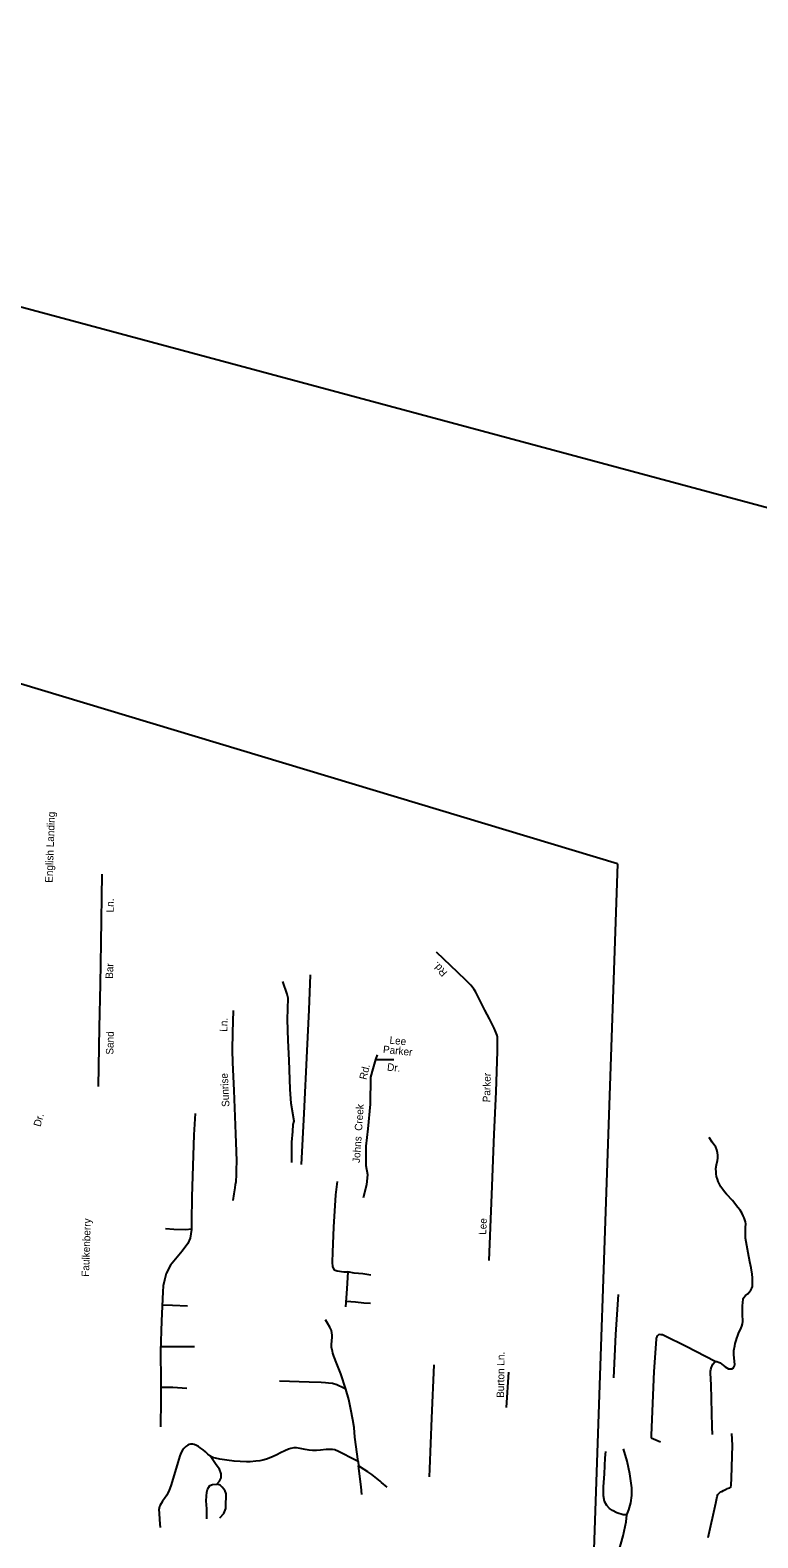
# Model space of a CAD drawing. Extents: x 2308163 to 2335412, y -96774 to 127732.
# Drawn here: x 2322097.3 to 2322147.2, y 82546.6 to 82650.1 of the extents above; entities that cross this region are included whole.
import ezdxf

# ---------------------------------------------------------------- set-up
doc = ezdxf.new("R2010")
doc.units = 0
for name, color, linetype in [('Old_Level_10', 7, 'Continuous'), ('Old_Level_35', 7, 'Continuous'), ('Old_Level_63', 7, 'Continuous')]:
    doc.layers.add(name, color=color, linetype=linetype)

msp = doc.modelspace()

# ---------------------------------------------------------------- linework, layer by layer
at = {"layer": 'Old_Level_35'}
for p, q in [((2322139.92, 82553.69), (2322139.91, 82553.51)), ((2322139.91, 82553.51), (2322140.56, 82553.24)), ((2322144.11, 82553.73), (2322144.09, 82554.26)), ((2322119.81, 82551.88), (2322119.85, 82551.59)), ((2322120.02, 82550.15), (2322119.85, 82551.59)), ((2322124.71, 82550.84), (2322124.73, 82551.38)), ((2322120.08, 82549.62), (2322120.02, 82550.15)), ((2322106.2, 82547.89), (2322106.23, 82547.36))]:
    msp.add_line(p, q, dxfattribs=at)
for points in [[(2322102.02, 82577.61), (2322102.09, 82581.67), (2322102.15, 82584.64), (2322102.2, 82587.48), (2322102.26, 82592.18)], [(2322128.8, 82565.69), (2322128.98, 82570.2), (2322129.14, 82574.34), (2322129.28, 82577.26), (2322129.38, 82580.04), (2322129.38, 82580.27), (2322129.38, 82580.55), (2322129.38, 82580.82), (2322129.37, 82581.01), (2322129.34, 82581.12), (2322129.27, 82581.34), (2322129.15, 82581.61), (2322128.82, 82582.27), (2322128.51, 82582.86), (2322127.89, 82584.08), (2322127.78, 82584.28), (2322127.55, 82584.57), (2322127.21, 82584.92), (2322126.66, 82585.44), (2322125.18, 82586.83)], [(2322115.26, 82572.41), (2322115.26, 82573.15), (2322115.26, 82573.44), (2322115.28, 82573.63), (2322115.28, 82573.8), (2322115.34, 82574.53), (2322115.37, 82575), (2322115.42, 82575.25), (2322115.23, 82576.46), (2322115.16, 82577.44), (2322115.09, 82579.43), (2322115.01, 82580.78), (2322114.98, 82582.22), (2322115.02, 82583.68), (2322114.96, 82583.95), (2322114.66, 82584.82)], [(2322115.94, 82572.27), (2322116.11, 82575.76), (2322116.33, 82580.07), (2322116.46, 82582.88), (2322116.56, 82585.28)], [(2322111.42, 82574.36), (2322111.32, 82577.35), (2322111.22, 82579.26), (2322111.2, 82580.1), (2322111.22, 82581.32), (2322111.28, 82582.84)], [(2322121.12, 82579.8), (2322121.01, 82579.47), (2322120.83, 82578.84), (2322120.67, 82578.25), (2322120.65, 82576.41), (2322120.47, 82574.71), (2322120.35, 82573.53), (2322120.34, 82572.2), (2322120.46, 82571.58), (2322120.4, 82570.87), (2322120.17, 82569.99)], [(2322121.01, 82579.47), (2322122.26, 82579.46)], [(2322108.64, 82575.77), (2322108.56, 82574.31), (2322108.42, 82570.04), (2322108.4, 82568.35), (2322108.4, 82567.8), (2322108.3, 82567.22), (2322108.13, 82566.85), (2322107.75, 82566.32), (2322107.29, 82565.76), (2322106.96, 82565.37), (2322106.66, 82564.79), (2322106.53, 82564.32), (2322106.44, 82563.93), (2322106.42, 82563.54), (2322106.33, 82561.55), (2322106.27, 82559.43), (2322106.29, 82557.42), (2322106.29, 82556.09), (2322106.27, 82554.26)], [(2322111.24, 82569.8), (2322111.32, 82570.25), (2322111.39, 82570.66), (2322111.41, 82570.89), (2322111.45, 82571.09), (2322111.47, 82571.56), (2322111.48, 82571.89), (2322111.5, 82572.5), (2322111.48, 82573.16), (2322111.42, 82574.36)], [(2322144.3, 82558.75), (2322144.35, 82558.75), (2322144.42, 82558.75), (2322144.52, 82558.71), (2322144.66, 82558.65), (2322144.75, 82558.57), (2322144.99, 82558.39), (2322145.11, 82558.31), (2322145.21, 82558.25), (2322145.34, 82558.24), (2322145.45, 82558.25), (2322145.55, 82558.31), (2322145.59, 82558.37), (2322145.63, 82558.45), (2322145.65, 82558.54), (2322145.58, 82559.2), (2322145.59, 82559.37), (2322145.59, 82559.5), (2322145.65, 82559.83), (2322145.68, 82559.98), (2322145.73, 82560.2), (2322145.78, 82560.35), (2322145.85, 82560.53), (2322145.93, 82560.73), (2322146.03, 82560.94), (2322146.13, 82561.18), (2322146.18, 82561.34), (2322146.2, 82561.49), (2322146.19, 82561.61), (2322146.18, 82561.88), (2322146.17, 82562.16), (2322146.18, 82562.53), (2322146.19, 82562.85), (2322146.21, 82562.97), (2322146.22, 82563.07), (2322146.26, 82563.15), (2322146.39, 82563.28), (2322146.53, 82563.4), (2322146.64, 82563.51), (2322146.74, 82563.65), (2322146.81, 82563.77), (2322146.85, 82563.9), (2322146.86, 82564.06), (2322146.86, 82564.24), (2322146.85, 82564.49), (2322146.83, 82564.74), (2322146.76, 82565.18), (2322146.67, 82565.59), (2322146.57, 82566.21), (2322146.43, 82566.97), (2322146.39, 82567.21), (2322146.38, 82567.39), (2322146.37, 82567.63), (2322146.39, 82567.95), (2322146.4, 82568.19), (2322146.38, 82568.33), (2322146.34, 82568.47), (2322146.29, 82568.6), (2322146.22, 82568.75), (2322146.12, 82568.96), (2322146.01, 82569.13), (2322145.86, 82569.32), (2322145.5, 82569.79), (2322145.08, 82570.24), (2322144.95, 82570.39), (2322144.83, 82570.55), (2322144.69, 82570.74), (2322144.6, 82570.91), (2322144.51, 82571.1), (2322144.45, 82571.25), (2322144.4, 82571.45), (2322144.37, 82571.63), (2322144.36, 82571.75), (2322144.35, 82571.99), (2322144.38, 82572.24), (2322144.45, 82572.55), (2322144.48, 82572.7), (2322144.49, 82572.91), (2322144.46, 82573.06), (2322144.41, 82573.28), (2322144.35, 82573.46), (2322144.09, 82573.81), (2322143.88, 82574.11)], [(2322118.37, 82571.09), (2322118.27, 82570.19), (2322118.13, 82567.96), (2322118.05, 82566.26), (2322118.03, 82565.57), (2322118.06, 82565.24), (2322118.17, 82565.05), (2322118.37, 82564.97), (2322118.84, 82564.91), (2322119.1, 82564.9)], [(2322108.4, 82567.84), (2322107.99, 82567.78), (2322107.17, 82567.81), (2322106.6, 82567.86)], [(2322119.1, 82564.9), (2322119.04, 82563.74), (2322118.96, 82562.49)], [(2322120.68, 82564.68), (2322120.14, 82564.76), (2322119.55, 82564.82), (2322119.1, 82564.9)], [(2322118.99, 82562.9), (2322119.64, 82562.85), (2322120.21, 82562.77), (2322120.66, 82562.75)], [(2322137.34, 82557.63), (2322137.49, 82560.6), (2322137.66, 82563.35)], [(2322106.38, 82562.63), (2322107.08, 82562.62), (2322108.11, 82562.58)], [(2322118.98, 82556.84), (2322118.62, 82557.9), (2322118.35, 82558.58), (2322118.16, 82559.11), (2322118.09, 82559.31), (2322118.06, 82559.45), (2322118.03, 82559.52), (2322118, 82559.73), (2322117.99, 82559.92), (2322118.01, 82560.17), (2322118.03, 82560.41), (2322118.04, 82560.56), (2322118.02, 82560.71), (2322117.98, 82560.87), (2322117.88, 82561.11), (2322117.71, 82561.38), (2322117.57, 82561.6)], [(2322144.3, 82558.75), (2322142.31, 82559.78), (2322140.83, 82560.51), (2322140.68, 82560.57), (2322140.6, 82560.59), (2322140.51, 82560.6), (2322140.41, 82560.57), (2322140.35, 82560.52), (2322140.3, 82560.45), (2322140.26, 82560.35), (2322140.26, 82560.29), (2322140.1, 82558.07), (2322139.92, 82553.69)], [(2322106.28, 82559.77), (2322106.98, 82559.78), (2322108.59, 82559.78)], [(2322124.73, 82551.38), (2322124.87, 82554.87), (2322125.04, 82558.53)], [(2322144.09, 82554.26), (2322144.02, 82557.14), (2322143.99, 82557.94), (2322143.99, 82558.08), (2322144, 82558.2), (2322144.05, 82558.35), (2322144.09, 82558.46), (2322144.15, 82558.56), (2322144.3, 82558.75)], [(2322129.99, 82555.59), (2322130.15, 82558.01)], [(2322108.08, 82556.9), (2322107.1, 82556.96), (2322106.29, 82556.97)], [(2322118.98, 82556.84), (2322118.7, 82556.98), (2322118.5, 82557.07), (2322118.35, 82557.14), (2322118.05, 82557.23), (2322117.79, 82557.26), (2322117.57, 82557.28), (2322117.27, 82557.31), (2322116.46, 82557.33), (2322114.43, 82557.39)], [(2322119.81, 82551.88), (2322119.6, 82553.55), (2322119.54, 82554.22), (2322119.46, 82554.74), (2322119.32, 82555.46), (2322119.17, 82556.15), (2322118.98, 82556.84)], [(2322143.83, 82546.68), (2322144.35, 82549.04), (2322144.43, 82549.49), (2322144.49, 82549.63), (2322144.59, 82549.74), (2322144.67, 82549.8), (2322144.75, 82549.84), (2322144.87, 82549.9), (2322145, 82549.96), (2322145.09, 82550.02), (2322145.13, 82550.03), (2322145.22, 82550.05), (2322145.31, 82550.08), (2322145.37, 82550.13), (2322145.39, 82550.27), (2322145.43, 82550.75), (2322145.48, 82553), (2322145.44, 82553.82)], [(2322109.36, 82552.54), (2322109.19, 82552.68), (2322109.06, 82552.77), (2322108.99, 82552.83), (2322108.88, 82552.92), (2322108.74, 82552.99), (2322108.57, 82553.05), (2322108.47, 82553.08), (2322108.32, 82553.08), (2322108.23, 82553.06), (2322108.13, 82553.01), (2322108.01, 82552.92), (2322107.86, 82552.78), (2322107.78, 82552.67), (2322107.69, 82552.5), (2322107.6, 82552.27), (2322107.45, 82551.81), (2322107.07, 82550.52), (2322106.97, 82550.21), (2322106.86, 82549.93), (2322106.74, 82549.68), (2322106.69, 82549.58), (2322106.54, 82549.35), (2322106.41, 82549.16), (2322106.32, 82549.01), (2322106.23, 82548.9), (2322106.2, 82548.81), (2322106.17, 82548.68), (2322106.16, 82548.57), (2322106.18, 82548.37), (2322106.2, 82547.89)], [(2322119.81, 82551.88), (2322119.32, 82552.15), (2322118.79, 82552.42), (2322118.47, 82552.57), (2322118.21, 82552.68), (2322118.05, 82552.71), (2322117.87, 82552.71), (2322117.63, 82552.7), (2322117.24, 82552.67), (2322116.96, 82552.65), (2322116.69, 82552.65), (2322116.46, 82552.67), (2322116.18, 82552.71), (2322115.85, 82552.78), (2322115.58, 82552.82), (2322115.4, 82552.82), (2322115.21, 82552.78), (2322115.05, 82552.73), (2322114.78, 82552.63), (2322114.5, 82552.48), (2322114.24, 82552.35), (2322113.99, 82552.23), (2322113.72, 82552.11), (2322113.53, 82552.04), (2322113.27, 82551.97), (2322113.08, 82551.94), (2322112.81, 82551.9), (2322112.42, 82551.87), (2322112.16, 82551.87), (2322111.72, 82551.88), (2322111.31, 82551.92), (2322110.81, 82551.99), (2322110.33, 82552.05), (2322110.03, 82552.11), (2322109.9, 82552.15), (2322109.77, 82552.21), (2322109.66, 82552.27), (2322109.51, 82552.38), (2322109.36, 82552.54)], [(2322138.25, 82548.22), (2322137.99, 82548.23), (2322137.55, 82548.36), (2322137.26, 82548.52), (2322137.06, 82548.67), (2322136.86, 82548.88), (2322136.72, 82549.15), (2322136.64, 82549.54), (2322136.64, 82550.16), (2322136.7, 82551.04), (2322136.76, 82552.13), (2322136.81, 82552.58)], [(2322138.25, 82548.22), (2322138.38, 82548.57), (2322138.52, 82549.06), (2322138.59, 82549.56), (2322138.58, 82550.09), (2322138.44, 82551.04), (2322138.26, 82551.9), (2322138.02, 82552.76)], [(2322110.34, 82548.02), (2322110.61, 82548.33), (2322110.74, 82548.66), (2322110.75, 82549.08), (2322110.77, 82549.37), (2322110.77, 82549.53), (2322110.77, 82549.66), (2322110.75, 82549.74), (2322110.69, 82549.86), (2322110.61, 82549.99), (2322110.49, 82550.13), (2322110.35, 82550.27), (2322110.12, 82550.33), (2322110.3, 82550.53), (2322110.43, 82550.76), (2322110.43, 82551.04), (2322110.32, 82551.37), (2322110.07, 82551.67), (2322109.66, 82552.27)], [(2322121.32, 82550.53), (2322121.22, 82550.62), (2322120.99, 82550.81), (2322120.76, 82550.99), (2322120.48, 82551.18), (2322120.22, 82551.35), (2322119.85, 82551.59)], [(2322109.44, 82547.95), (2322109.45, 82548.65), (2322109.4, 82549.19), (2322109.41, 82549.52), (2322109.43, 82549.78), (2322109.48, 82549.96), (2322109.57, 82550.12), (2322109.65, 82550.23), (2322109.83, 82550.3), (2322110.12, 82550.33)], [(2322121.81, 82550.12), (2322121.41, 82550.45), (2322121.32, 82550.53)], [(2322137.51, 82544.73), (2322137.63, 82545.49), (2322137.99, 82546.78), (2322138.2, 82547.75), (2322138.25, 82548.22)]]:
    msp.add_lwpolyline(points, dxfattribs=at)
at = {"layer": 'Old_Level_63'}
msp.add_line((2322137.61, 82592.9), (2322074.1, 82612.06), dxfattribs=at)
for points in [[(2322237.3, 82590.26), (2322216.65, 82598.81), (2322026.04, 82650.1)], [(2322137.61, 82592.9), (2322134.07, 82490.21), (2322069.96, 82492.24), (2322074.1, 82612.06)]]:
    msp.add_lwpolyline(points, dxfattribs=at)

# ---------------------------------------------------------------- texts
at = {"layer": 'Old_Level_10'}
for s, height, rotation, p in [('English Landing', 0.5126, 88.0247, (2322098.86, 82591.59)), ('Ln.', 0.513, 89.0989, (2322103.05, 82589.56)), ('Bar', 0.513, 88.1197, (2322103, 82585)), ('Rd.', 0.513, 132.9634, (2322125.97, 82585.45)), ('Sand', 0.513, 88.9158, (2322103.03, 82579.8)), ('Ln.', 0.513, 88.0624, (2322110.84, 82581.37)), ('Parker', 0.513, 354.2925, (2322121.5, 82579.92)), ('Lee', 0.513, 354.2925, (2322121.95, 82580.56)), ('Dr.', 0.513, 354.2925, (2322121.78, 82578.71)), ('Sunrise', 0.513, 92.8193, (2322110.99, 82576.23)), ('Rd.', 0.513, 76.1913, (2322120.38, 82578.05)), ('Parker', 0.513, 88.7193, (2322128.87, 82576.53)), ('Johns  Creek ', 0.5126, 86.0484, (2322119.93, 82572.36)), ('Dr.', 0.513, 74.2787, (2322098.03, 82574.82)), ('Faulkenberry', 0.5126, 88.1377, (2322101.36, 82564.56)), ('Lee', 0.513, 86.8925, (2322128.59, 82567.43)), ('Burton Ln.', 0.513, 89.2977, (2322129.82, 82556.25))]:
    msp.add_text(s, height=height, rotation=rotation, dxfattribs=at).set_placement(p)

doc.saveas('drawing.dxf')
